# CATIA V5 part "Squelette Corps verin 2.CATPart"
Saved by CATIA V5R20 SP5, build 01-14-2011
Part number: Squelette Corps verin 2
Bounding box of the stored display mesh (mm): x -255.709 to -200, y -175 to -35.728, z 0 to 20
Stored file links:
  U:\CFAO\Thinkmotion\Squelette Corps verin 2.CATPart
  U:\CFAO\Thinkmotion\Bras Articule.CATProduct
  U:\CFAO\Thinkmotion\Squelette general.CATPart
  U:\CFAO\Thinkmotion\Squelette Bielle principale.CATPart
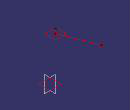
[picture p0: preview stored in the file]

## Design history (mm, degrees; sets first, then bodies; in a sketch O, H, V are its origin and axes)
Set1
  Line1: type Normal, RefPoint Point1, RefSkin Plane2, Start 0, End 20
  Line2: type PtPt, FirstPoint Point1, SecondPoint Point2
  Plane1: type OffsetPt, RefPlane xy-plane, RefPoint Point1
Set2
  Plane2: linked copy from another document
  Point1: linked copy from another document
  Point2: linked copy from another document
Body1 (main body)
